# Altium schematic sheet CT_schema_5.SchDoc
size 296 x 198 mm
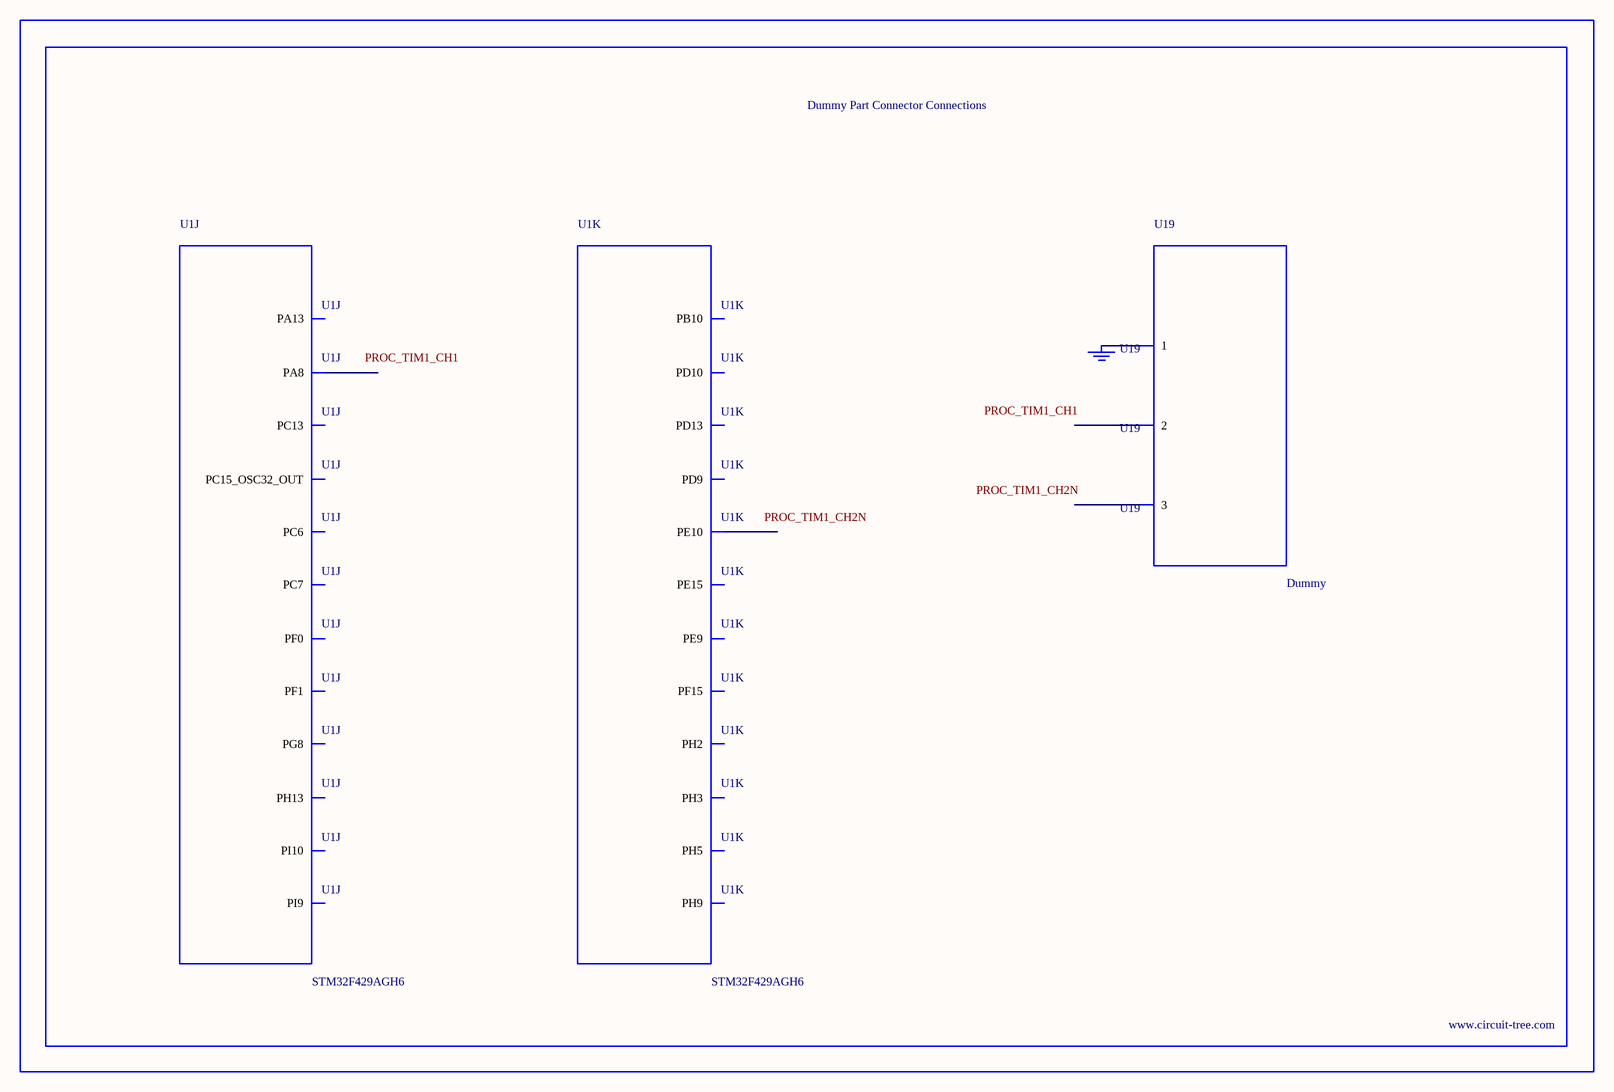
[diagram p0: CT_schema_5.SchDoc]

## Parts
BORDER4  (no value)
GND_INSTANCE_4_0  (no value)
U1  STM32F429AGH6  [UFBGA169]  (parts J,K of 11)
U19  Dummy  [DUMMY_PACKAGE_243]

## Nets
NetGND_INSTANCE_4_0_0: GND_INSTANCE_4_0.0(GND) U19.1

Not connected (* = marked no-connect by the designer): U1 D13(PH13) E2(PI9) E3(PI10) E4(PC13) E12(PA13) E13(PA8) F1(PC15_OSC32_OUT) F2(PF0) F3(PF1) F9(PC6) F10(PC7) F13(PG8) K8(PE9) K9(PE15) K10(PH9) K11(PD10) K12(PD13) K13(PD9) L1(PH3) L2(PH2) L3(PH5) L7(PF15) L8(PE10) L9(PB10); U19 2 3

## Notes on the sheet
- Labels drawn without touching a wire or pin: PROC_TIM1_CH1, PROC_TIM1_CH2N

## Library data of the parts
BORDER4 = BORDER_PAGE4
GND_INSTANCE_4_0 = GND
